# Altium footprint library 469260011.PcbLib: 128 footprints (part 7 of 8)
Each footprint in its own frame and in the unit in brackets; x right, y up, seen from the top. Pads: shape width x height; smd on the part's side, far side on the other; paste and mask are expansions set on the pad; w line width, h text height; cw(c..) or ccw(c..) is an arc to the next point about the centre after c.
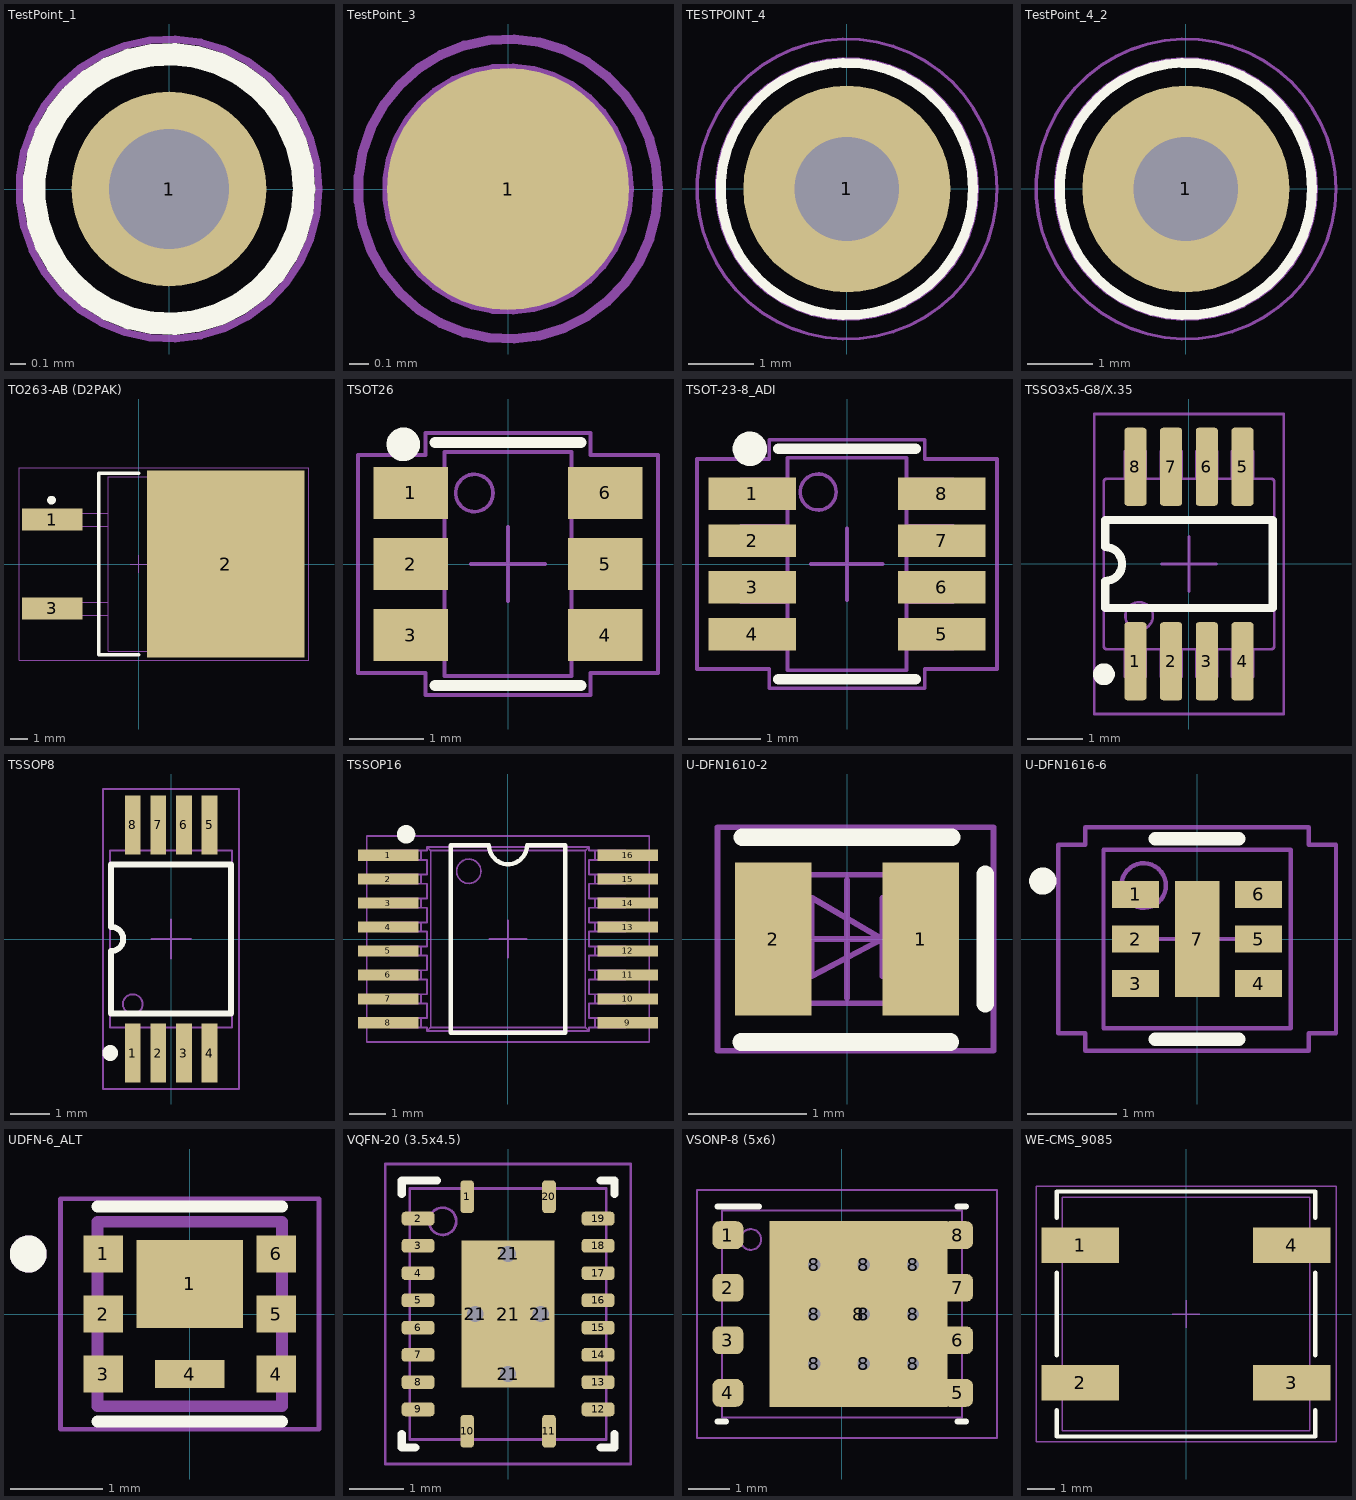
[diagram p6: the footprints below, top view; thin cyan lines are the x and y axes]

## TestPoint_1 [mm]
height 0.025
pads (1):
  round 1.3 hole 0.8: 1(0,0)
Top Overlay:
  circle w0.15: c0,0 r0.9
Top Assembly:
  circle w0.05: c0,0 r1
  text ".Designator" at -2.252,-0.226 h1
Top Courtyard:
  circle w0.05: c0,0 r1
  lines w0.05: -0.5,0 0.5,0 ; -0.002,-0.5 -0.002,0.5 ; -0.002,0 0,0

## TestPoint_3 [mm]
height 0.025
pads (1):
  round 1.25 smd paste-1.25: 1(0,0)
Top Assembly:
  circle w0.05: c0,0 r0.625
  text ".Designator" at -2.252,-0.226 h1
Top Courtyard:
  circle w0.05: c0,0 r0.775
  lines w0.05: -0.5,0 0.5,0 ; 0,-0.5 0,0.5

## TESTPOINT_4 [mil]
height 1
pads (1):
  round 125 hole 63: 1(0,0)
Top Overlay:
  circle w5.91: c0,0 r76.17
Top Assembly:
  circle w1.97: c0.07,0 r78.74
  text ".Designator" at -88.6,-8.9 h39.37
Top Courtyard:
  circle w1.97: c0.07,0 r90.55
  lines w1.97: -19.62,0 19.75,0 ; 0,-19.69 0,19.68
3D body "keystone-PN5281.STEP": height 319.63, standoff -125, extent -62.04,-62.5 62.04,62.5

## TestPoint_4_2 [mil]
pads (1):
  round 125 hole 63: 1(0,0)
Top Overlay:
  circle w5.91: c0,0 r76.17
Top Assembly:
  circle w1.97: c0.07,0 r78.74
  text ".Designator" at -88.6,-8.9 h39.37
Top Courtyard:
  circle w1.97: c0.07,0 r90.55
  lines w1.97: -19.62,0 19.75,0 ; 0,-19.69 0,19.68
3D body "keystone-PN5281.STEP": height 319.63, standoff -125, extent -62.04,-62.5 62.04,62.5

## TO263-AB (D2PAK) [mil] "D2PAK (2 Leads + Tab), TO-263AB, Body 9.4x10.2mm, Pitch 2.54mm, Lead Span 14.3mm, IPC Medium Density"
height 183.07
pads (3):
  rect 136.18x49.88 smd: 1(-195.3,100) 3(-195.3,-100)
  rect 355x420 smd: 2(195.3,0)
Top Overlay:
  circle w9.84: c-196.85,143.7 r4.92
  lines w7.87: -0.41,-204.72 -90.96,-204.72 -90.96,204.72 -0.41,204.72
Top Assembly:
  lines w1.97: -68.9,-115.35 -226.38,-115.35 -226.38,-85.76 -68.9,-85.76 ; -68.9,84.65 -226.38,84.65 -226.38,114.24 -68.9,114.24 ; 297.23,-196.85 297.23,196.85 ; -68.9,-196.85 326.77,-196.85 363.39,-160.24 363.39,158.27 324.8,196.85 -68.9,196.85 -68.9,-196.85
  text ".Designator" at -88.67,-8.9 h39.37
Top Courtyard:
  lines w1.97: -19.68,0 19.68,0 ; 0,-19.68 0,19.68 ; -270.1,-216.54 -270.1,216.54 381.89,216.54 381.89,-216.54 -270.1,-216.54
3D body "11-User Library-TO263-3S.step": height 188.3, standoff -0.68, extent -253.54,-196.85 363.39,196.85

## TSOT26 [mm] "TSOT-26, SOT-23-6 Thin, TSOT-23-6"
height 1
pads (6):
  rect 1x0.7 smd paste+0 mask+0: 1(-1.3,0.95) 2(-1.3,0) 3(-1.3,-0.95) 4(1.3,-0.95) 5(1.3,0) 6(1.3,0.95)
Top Overlay:
  circle w0.25: c-1.4,1.6 r0.1
  lines w0.15: -0.978,-1.626 0.978,-1.626 ; -0.978,1.626 0.978,1.626
Top Assembly:
  circle w0.05: c-0.45,0.95 r0.25
  lines w0.05: -1.397,-1.179 -1.397,-0.721 -0.851,-0.721 -0.851,-1.179 -1.397,-1.179 ; -1.397,-0.229 -1.397,0.229 -0.851,0.229 -0.851,-0.229 -1.397,-0.229 ; -1.397,0.721 -0.851,0.721 -0.851,1.179 -1.397,1.179 -1.397,0.721 ; -0.851,-1.499 0.851,-1.499 0.851,1.499 -0.851,1.499 -0.851,-1.499 ; 0.851,-1.179 0.851,-0.721 1.397,-0.721 1.397,-1.179 0.851,-1.179 ; 0.851,-0.229 0.851,0.229 1.397,0.229 1.397,-0.229 0.851,-0.229 ; 0.851,0.721 1.397,0.721 1.397,1.179 0.851,1.179 0.851,0.721
  text ".Designator" at -3.378,-0.339 h1.5
Top Courtyard:
  lines w0.05: -0.5,0 0.5,0 ; 0,-0.5 0,0.5 ; -2.007,-1.458 -2.007,1.458 -1.105,1.458 -1.105,1.753 1.105,1.753 1.105,1.458 2.007,1.458 2.007,-1.458 1.105,-1.458 1.105,-1.753 -1.105,-1.753 -1.105,-1.458 -2.007,-1.458
3D body "AP22615AWU-7.step": height 1, standoff 0, extent -1.45,-1.45 1.45,1.45

## TSOT-23-8_ADI [mm] "TS8 Package ADI, 8-Lead Plastic TSOT-23"
height 1.1
pads (8):
  rect 1.22x0.45 smd paste-0.05: 1(-1.315,0.975) 2(-1.315,0.325) 3(-1.315,-0.325) 4(-1.315,-0.975) 5(1.315,-0.975) 6(1.315,-0.325) 7(1.315,0.325) 8(1.315,0.975)
Top Overlay:
  circle w0.254: c-1.35,1.6 r0.112
  lines w0.15: -0.953,-1.6 0.953,-1.6 ; -0.953,1.6 0.953,1.6
Top Assembly:
  circle w0.05: c-0.4,1 r0.25
  lines w0.05: -1.473,-1.178 -1.473,-0.772 -0.826,-0.772 -0.826,-1.178 -1.473,-1.178 ; -1.473,-0.528 -1.473,-0.122 -0.826,-0.122 -0.826,-0.528 -1.473,-0.528 ; -1.473,0.122 -1.473,0.528 -0.826,0.528 -0.826,0.122 -1.473,0.122 ; -1.473,0.772 -1.473,1.178 -0.826,1.178 -0.826,0.772 -1.473,0.772 ; -0.826,-1.473 -0.826,1.473 0.826,1.473 0.826,-1.473 -0.826,-1.473 ; 0.826,-1.178 1.473,-1.178 1.473,-0.772 0.826,-0.772 0.826,-1.178 ; 0.826,-0.528 1.473,-0.528 1.473,-0.122 0.826,-0.122 0.826,-0.528 ; 0.826,0.122 1.473,0.122 1.473,0.528 0.826,0.528 0.826,0.122 ; 0.826,0.772 1.473,0.772 1.473,1.178 0.826,1.178 0.826,0.772
  text ".Designator" at -2.252,-0.226 h1
Top Courtyard:
  lines w0.05: -0.501,0 0.499,0 ; 0,-0.501 0,0.499 ; -2.083,-1.458 -1.079,-1.458 -1.079,-1.727 1.079,-1.727 1.079,-1.458 2.083,-1.458 2.083,1.458 1.079,1.458 1.079,1.727 -1.079,1.727 -1.079,1.458 -2.083,1.458 -2.083,-1.458
3D body "LTC2954CTS8-2_TRMPBF.step": height 1, standoff 0, extent -1.4,-1.45 1.4,1.45

## TSSO3x5-G8/X.35 [mm] "TSSOP-8P065 Shrink Small Outline; 8 Leads; Body Width 3 mm; Pitch 0.65 mm"
height 1.3
pads (8):
  rrect25% 0.4x1.42 smd: 1(-0.975,-1.77) 2(-0.325,-1.77) 3(0.325,-1.77) 4(0.975,-1.77) 5(0.975,1.77) 6(0.325,1.77) 7(-0.325,1.77) 8(-0.975,1.77)
Top Overlay:
  circle w0.2: c-1.549,-2.007 r0.1
  lines w0.15: -1.525,-0.8 -1.525,-0.308 ccw(c-1.525,0) -1.525,0.308 -1.525,0.8 1.525,0.8 1.525,-0.8 -1.525,-0.8
Top Assembly:
  circle w0.05: c-0.907,-0.946 r0.25
  lines w0.05: -1.55,-1.5 ccw(c-1.5,-1.5) -1.5,-1.55 ; -1.55,-1.5 ccw(c-1.5,-1.5) -1.55,-1.5 ; -1.55,-1.5 -1.55,1.5 ; -1.55,1.5 cw(c-1.5,1.5) -1.5,1.55 ; -1.55,1.5 ccw(c-1.5,1.5) -1.55,1.5 ; -1.5,-1.55 ccw(c-1.5,-1.5) -1.5,-1.55 ; -1.5,-1.55 -1.165,-1.55 ; -1.5,1.55 ccw(c-1.5,1.5) -1.5,1.55 ; -1.5,1.55 -1.165,1.55 ; -1.165,-1.92 -1.165,-1.825 ; -1.165,-1.92 -1.165,-2.05 -0.785,-2.05 -0.785,-1.92 ; -1.165,-1.92 -0.785,-1.92 ; -1.165,-1.825 -1.165,-1.58 ; -1.165,-1.825 -0.785,-1.825 ; -1.165,-1.58 -1.165,-1.55 ; -1.165,-1.58 -0.785,-1.58 ; -1.165,-1.55 -0.785,-1.55 ; -1.165,1.55 -0.785,1.55 ; -1.165,1.55 -1.165,1.58 ; -1.165,1.58 -1.165,1.825 ; -1.165,1.58 -0.785,1.58 ; -1.165,1.825 -0.785,1.825 ; -1.165,1.825 -1.165,1.92 ; -1.165,1.92 -1.165,2.05 -0.785,2.05 -0.785,1.92 ; -1.165,1.92 -0.785,1.92 ; -0.785,-1.92 -0.785,-1.825 ; -0.785,-1.825 -0.785,-1.58 ; -0.785,-1.58 -0.785,-1.55 ; -0.785,-1.55 -0.515,-1.55 ; -0.785,1.55 -0.515,1.55 ; -0.785,1.55 -0.785,1.58 ; -0.785,1.58 -0.785,1.825 ; -0.785,1.825 -0.785,1.92 ; -0.515,-1.92 -0.515,-1.825 ; -0.515,-1.92 -0.515,-2.05 -0.135,-2.05 -0.135,-1.92 ; -0.515,-1.92 -0.135,-1.92 ; -0.515,-1.825 -0.515,-1.58 ; -0.515,-1.825 -0.135,-1.825 ; -0.515,-1.58 -0.515,-1.55 ; -0.515,-1.58 -0.135,-1.58 ; -0.515,-1.55 -0.135,-1.55 ; -0.515,1.55 -0.135,1.55 ; -0.515,1.55 -0.515,1.58 ; -0.515,1.58 -0.515,1.825 ; -0.515,1.58 -0.135,1.58 ; -0.515,1.825 -0.135,1.825 ; -0.515,1.825 -0.515,1.92 ; -0.515,1.92 -0.515,2.05 -0.135,2.05 -0.135,1.92 ; -0.515,1.92 -0.135,1.92 ; -0.135,-1.92 -0.135,-1.825 ; -0.135,-1.825 -0.135,-1.58 ; -0.135,-1.58 -0.135,-1.55 ; -0.135,-1.55 0.135,-1.55 ; -0.135,1.55 0.135,1.55 ; -0.135,1.55 -0.135,1.58 ; -0.135,1.58 -0.135,1.825 ; -0.135,1.825 -0.135,1.92 ; 0.135,-1.92 0.135,-1.825 ; 0.135,-1.92 0.135,-2.05 0.515,-2.05 0.515,-1.92 ; 0.135,-1.92 0.515,-1.92 ; 0.135,-1.825 0.135,-1.58 ; 0.135,-1.825 0.515,-1.825 ; 0.135,-1.58 0.135,-1.55 ; 0.135,-1.58 0.515,-1.58 ; 0.135,-1.55 0.515,-1.55 ; 0.135,1.55 0.515,1.55 ; 0.135,1.55 0.135,1.58 ; 0.135,1.58 0.135,1.825 ; 0.135,1.58 0.515,1.58 ; 0.135,1.825 0.515,1.825 ; 0.135,1.825 0.135,1.92 ; 0.135,1.92 0.135,2.05 0.515,2.05 0.515,1.92 ; 0.135,1.92 0.515,1.92 ; 0.515,-1.92 0.515,-1.825 ; 0.515,-1.825 0.515,-1.58 ; 0.515,-1.58 0.515,-1.55 ; 0.515,-1.55 0.785,-1.55 ; 0.515,1.55 0.785,1.55 ; 0.515,1.55 0.515,1.58 ; 0.515,1.58 0.515,1.825 ; 0.515,1.825 0.515,1.92 ; 0.785,-1.92 0.785,-1.825 ; 0.785,-1.92 0.785,-2.05 1.165,-2.05 1.165,-1.92 ; 0.785,-1.92 1.165,-1.92 ; 0.785,-1.825 0.785,-1.58 ; 0.785,-1.825 1.165,-1.825 ; 0.785,-1.58 0.785,-1.55 ; 0.785,-1.58 1.165,-1.58 ; 0.785,-1.55 1.165,-1.55 ; 0.785,1.55 1.165,1.55 ; 0.785,1.55 0.785,1.58 ; 0.785,1.58 0.785,1.825 ; 0.785,1.58 1.165,1.58 ; 0.785,1.825 1.165,1.825 ; 0.785,1.825 0.785,1.92 ; 0.785,1.92 0.785,2.05 1.165,2.05 1.165,1.92 ; 0.785,1.92 1.165,1.92 ; 1.165,-1.92 1.165,-1.825 ; 1.165,-1.825 1.165,-1.58 ; 1.165,-1.58 1.165,-1.55 ; 1.165,-1.55 1.5,-1.55 ; 1.165,1.55 1.5,1.55 ; 1.165,1.55 1.165,1.58 ; 1.165,1.58 1.165,1.825 ; 1.165,1.825 1.165,1.92 ; 1.5,-1.55 ccw(c1.5,-1.5) 1.55,-1.5 ; 1.5,-1.55 ccw(c1.5,-1.5) 1.5,-1.55 ; 1.5,1.55 cw(c1.5,1.5) 1.55,1.5 ; 1.5,1.55 ccw(c1.5,1.5) 1.5,1.55 ; 1.55,-1.5 ccw(c1.5,-1.5) 1.55,-1.5 ; 1.55,-1.5 1.55,1.5 ; 1.55,1.5 ccw(c1.5,1.5) 1.55,1.5
  text ".Designator" at -2.252,-0.226 h1
Top Courtyard:
  lines w0.05: -0.5,0 0.5,0 ; 0,-0.5 0,0.5 ; -1.725,-2.73 -1.725,2.73 1.725,2.73 1.725,-2.73 -1.725,-2.73
3D body "PCA9306DCTR.step": height 1.3, standoff 0, extent -1.475,-2 1.475,2

## TSSOP8 [mm] "Shrink Small Outline; 8 Leads; Body Width 3 mm; Pitch 0.65 mm"
height 1.11
pads (8):
  rect 0.4x1.5 smd: 1(-0.975,-2.9) 2(-0.325,-2.9) 3(0.325,-2.9) 4(0.975,-2.9) 5(0.975,2.9) 6(0.325,2.9) 7(-0.325,2.9) 8(-0.975,2.9)
Top Overlay:
  circle w0.2: c-1.549,-2.896 r0.1
  lines w0.15: -1.525,-1.89 1.525,-1.89 1.525,1.89 -1.525,1.89 -1.525,0.308 cw(c-1.525,0) -1.525,-0.308 -1.525,-1.89
Top Assembly:
  drawing of 265 lines, arcs and shapes, not listed
  text ".Designator" at -2.252,-0.226 h1
Top Courtyard:
  lines w0.05: -0.5,0 0.5,0 ; 0,-0.5 0,0.5 ; -1.725,-3.81 -1.725,3.81 1.725,3.81 1.725,-3.81 -1.725,-3.81
3D body "SOP8P65_300X640X120L60X24N.step": height 1.2, standoff 0, extent -1.5,-3.2 1.5,3.2

## TSSOP16 [mm]
height 1.2
pads (16):
  rect 1.65x0.3 smd: 1(-3.25,2.275) 2(-3.25,1.625) 3(-3.25,0.975) 4(-3.25,0.325) 5(-3.25,-0.325) 6(-3.25,-0.975) 7(-3.25,-1.625) 8(-3.25,-2.275) 9(3.25,-2.275) 10(3.25,-1.625) 11(3.25,-0.975) 12(3.25,-0.325) 13(3.25,0.325) 14(3.25,0.975) 15(3.25,1.625) 16(3.25,2.275)
Top Overlay:
  circle w0.25: c-2.769,2.845 r0.125
  lines w0.12: -1.55,-2.55 -1.55,2.55 -0.517,2.55 ccw(c0,2.55) 0.517,2.55 1.55,2.55 1.55,-2.55 -1.55,-2.55
Top Assembly:
  drawing of 269 lines, arcs and shapes, not listed
  text ".Designator" at -0.226,2.252 h1
Top Courtyard:
  lines w0.05: -0.5,0 0.5,0 ; 0,-0.5 0,0.5 ; -3.835,-2.794 -3.835,2.794 3.835,2.794 3.835,-2.794 -3.835,-2.794
3D body "TSSOP16_STM.step": height 1.2, standoff 0, extent -3.302,-2.553 3.302,2.553

## U-DFN1610-2 [mm] "U-DFN1610-2 (Type B) - 1.62 x 1.05 mm -  DIO"
height 0.55
pads (2):
  rect 0.65x1.3 smd: 1(0.625,0) 2(-0.625,0)
Top Overlay:
  lines w0.15: -0.9,-0.875 0.878,-0.875 ; -0.889,0.864 0.889,0.864 ; 1.175,-0.55 1.175,0.55
Top Assembly:
  lines w0.05: -0.3,0.346 -0.3,-0.316 0.3,0 -0.3,0.35 ; 0.3,-0.316 0.3,0.35 ; -0.838,-0.546 -0.838,0.546 0.838,0.546 0.838,-0.546 -0.838,-0.546
  text ".Designator" at -2.252,-0.226 h1
Top Courtyard:
  lines w0.05: -0.5,0 0.5,0 ; 0,-0.5 0,0.5 ; -1.1,-0.95 1.246,-0.95 1.246,0.95 -1.1,0.95 -1.1,-0.95
3D body "SMT_16A05L01_YAG.step": height 0.66, standoff 0, extent -0.838,-0.546 0.838,0.546

## U-DFN1616-6 [mm] "6-UFDFN Exposed Pad, 1.6 x 1.6 mm"
height 0.575
pads (7):
  rect 0.525x0.3 smd: 1(-0.69,0.5) 2(-0.69,0) 3(-0.69,-0.5) 4(0.69,-0.5) 5(0.69,0) 6(0.69,0.5)
  rect 0.5x1.3 smd: 7(0,0)
Top Overlay:
  circle w0.152: c-1.731,0.65 r0.076
  lines w0.152: -0.47,-1.127 0.47,-1.127 ; -0.47,1.127 0.47,1.127
Top Assembly:
  circle w0.05: c-0.6,0.6 r0.25
  lines w0.05: -1.05,-1 -1.05,1 1.05,1 1.05,-1 -1.05,-1
  text ".Designator" at -2.252,-0.226 h1
Top Courtyard:
  lines w0.05: -0.5,0 0.5,0 ; 0,-0.5 0,0.5 ; -1.559,-1.056 -1.559,1.056 -1.254,1.056 -1.254,1.254 1.254,1.254 1.254,1.056 1.559,1.056 1.559,-1.056 1.254,-1.056 1.254,-1.254 -1.254,-1.254 -1.254,-1.056 -1.559,-1.056
3D body "User Library-DFN6-2X2.step": height 0.75, standoff -0.05, extent -1.05,-1 1.05,1

## UDFN-6_ALT [mm]
pads (8):
  rect 0.425x0.4 smd: 1(-0.937,0.65) 2(-0.937,0) 3(-0.937,-0.65) 4(0.937,-0.65) 5(0.937,0) 6(0.937,0.65)
  rect 1.15x0.95 smd: 1(0,0.325)
  rect 0.75x0.3 smd: 4(0,-0.65)
Top Overlay:
  circle w0.2: c-1.75,0.65 r0.1
  lines w0.127: -1,-1.164 1,-1.164 ; -1,1.164 1,1.164
Top 3D Body:
  circle w0.2: c-1.75,0.65 r0.1
  lines w0.127: -1,-1 -1,1 1,1 1,-1 -1,-1
Top Courtyard:
  lines w0.05: -1.4,-1.25 -1.4,1.25 1.4,1.25 1.4,-1.25 -1.4,-1.25

## VQFN-20 (3.5x4.5) [mm] "RGY0020B, 20-VQFN (3.5x4.5)"
height 1
pads (25):
  rrect50% 0.25x0.6 smd paste+0 mask+0.051: 1(-0.75,2.15) 10(-0.75,-2.15) 11(0.75,-2.15) 20(0.75,2.15)
  rrect50% 0.6x0.25 smd paste+0 mask+0.051: 2(-1.65,1.75) 3(-1.65,1.25) 4(-1.65,0.75) 5(-1.65,0.25) 6(-1.65,-0.25) 7(-1.65,-0.75) 8(-1.65,-1.25) 9(-1.65,-1.75) 12(1.65,-1.75) 13(1.65,-1.25) 14(1.65,-0.75) 15(1.65,-0.25) 16(1.65,0.25) 17(1.65,0.75) 18(1.65,1.25) 19(1.65,1.75)
  round 0.5 hole 0.3 paste+0 mask+0.051: 21(-0.6,0) 21(0,-1.1) 21(0,1.1) 21(0.6,0)
  rect 1.7x2.7 smd paste-1.337 mask+0.051: 21(0,0)
Top Overlay:
  lines w0.15: -1.95,-2.2 -1.95,-2.45 -1.7,-2.45 ; -1.95,2.2 -1.95,2.45 -1.3,2.45 ; 1.7,-2.45 1.95,-2.45 1.95,-2.2 ; 1.7,2.45 1.95,2.45 1.95,2.2
Top Paste:
  region: -0.15,-0.15 -0.15,-1.288 -0.775,-1.288 -0.775,-0.15
  region: 0.15,-0.15 0.15,-1.288 0.774,-1.288 0.774,-0.15
  region: 0.15,0.15 0.15,1.288 0.774,1.288 0.774,0.15
  region: -0.15,0.15 -0.15,1.288 -0.774,1.288 -0.774,0.15
Top Assembly:
  circle w0.05: c-1.2,1.7 r0.25
  lines w0.05: -1.8,-2.3 1.8,-2.3 1.8,2.3 -1.8,2.3 -1.8,-2.3
  text ".Designator" at -2.252,-0.226 h1
Top Courtyard:
  lines w0.05: -0.5,0 0.5,0 ; 0,-0.5 0,0.5 ; -2.252,-2.75 2.25,-2.75 2.25,2.75 -2.252,2.75 -2.25,2.75 -2.252,-2.75
3D body "User Library-PVQFN-N20 (RGY).step": height 1, standoff 0, extent -1.81,-2.31 1.81,2.31

## VSONP-8 (5x6) [mm] "8-PowerTDFN, DQJ0008A"
height 1.1
pads (18):
  rrect50% 0.75x0.675 smd paste+0 mask-0.051: 1(-2.753,1.905) 2(-2.753,0.635) 3(-2.753,-0.635) 4(-2.753,-1.905) 5(2.8,-1.905) 6(2.8,-0.635) 7(2.8,0.635) 8(2.8,1.905)
  round 0.6 hole 0.3: 8(-0.67,-1.2) 8(-0.67,-0.005) 8(-0.67,1.19) 8(0.525,-1.2) 8(0.525,-0.005) 8(0.525,1.19) 8(1.72,-1.2) 8(1.72,-0.005) 8(1.72,1.19)
  rect 4.3x4.485 smd paste-2.272 mask-2.273: 8(0.405,0)
Top Layer:
  lines w0.25: 2.285,-0.635 2.8,-0.635 ; 2.36,0.635 2.8,0.635 ; 2.425,-1.905 2.8,-1.905 ; 2.435,1.905 2.8,1.905
Top Overlay:
  lines w0.15: -3,-2.6 -2.8,-2.6 ; -3,2.6 -2,2.6 ; 2.8,-2.6 3,-2.6 ; 2.8,2.6 3,2.6
Top Paste:
  drawing of 16 lines, arcs and shapes, not listed
Top Solder:
  region: 2.25,-0.43 2.25,-0.84 2.475,-0.84 2.475,-0.43
  region: 2.25,-1.7 2.25,-2.11 2.475,-2.11 2.475,-1.7
  region: 2.25,2.11 2.25,1.7 2.475,1.7 2.475,2.11
  region: 2.25,0.84 2.25,0.43 2.475,0.43 2.475,0.84
  region: -1.189,-2.193 -1.19,-2.183 -1.19,2.183 -1.189,2.193 -1.186,2.203 -1.181,2.212 -1.175,2.22 -1.167,2.226 -1.158,2.231 -1.148,2.234 -1.138,2.235 2.238,2.235 2.248,2.234 2.258,2.231 2.267,2.226 2.275,2.22 2.281,2.212 2.286,2.203 2.289,2.193 2.29,2.183 2.29,-2.183 2.289,-2.193 2.286,-2.203 2.281,-2.212 2.275,-2.22 2.267,-2.226 2.258,-2.231 2.248,-2.234 2.238,-2.235 -1.138,-2.235 -1.148,-2.234 -1.158,-2.231 -1.167,-2.226 -1.175,-2.22 -1.181,-2.212 -1.186,-2.203
Top Assembly:
  circle w0.05: c-2.2,1.8 r0.25
  lines w0.05: -2.9,-2.5 -2.9,2.5 2.9,2.5 2.9,-2.5 -2.9,-2.5
  text ".Designator" at -2.252,-0.226 h1
Top Courtyard:
  lines w0.05: -0.5,0 0.5,0 ; 0,-0.5 0,0.5 ; -3.5,-3 3.75,-3 3.75,3 -3.5,3 -3.5,-3
3D body "DQJ0008A.stp": height 1.15, standoff 0, extent -3.105,-2.45 3.155,2.45

## WE-CMS_9085 [mm] "Common Mode SMT Bead, body 9.00x8.50mm"
height 4.8
pads (4):
  rect 2.81x1.28 smd: 1(-3.85,2.5) 2(-3.85,-2.5) 3(3.85,-2.5) 4(3.85,2.5)
Top Overlay:
  lines w0.15: -4.7,-3.5 -4.7,-4.45 4.7,-4.45 4.7,-3.5 ; -4.7,-1.5 -4.7,1.5 ; -4.7,3.5 -4.7,4.45 4.7,4.45 4.7,3.5 ; 4.7,-1.5 4.7,1.5
Top Assembly:
  lines w0.05: -4.5,-4.25 4.5,-4.25 4.5,4.25 -4.5,4.25 -4.5,-4.25
  text ".Designator" at -3.378,-0.339 h1.5
Top Courtyard:
  lines w0.05: -0.5,0 0.5,0 ; 0,-0.5 0,0.5 ; -5.455,-4.65 -5.455,4.65 5.455,4.65 5.455,-4.65 -5.455,-4.65
3D body "Download_STP_WE-CMS-9085-7427523 (rev1).stp": height 4.63, standoff 0, extent -4.67,-4.25 4.67,4.25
